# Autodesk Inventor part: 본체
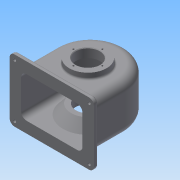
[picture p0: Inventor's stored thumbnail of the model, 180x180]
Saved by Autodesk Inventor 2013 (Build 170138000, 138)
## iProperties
Created: 2016-01
Part Number: 본체
Material: 일반
Document SubType Name: Modeling
Designer: mrc
Density: 1 g/cm^3
Author: mrc
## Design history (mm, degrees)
sketch "스케치3"
  geometry: L1 (-57, 0)-(-57, -64); L2 (57, 0)-(57, -64); L3 (-57, -64)-(57, -64); A1 r 57 centre (0, 0) between (57, 0) and (-57, 0); 1 further point
  constraints: 6 end point, 2 point on circle, 2 tangent, 1 centre point, 1 coincident, 1 parallel, 1 vertical
  dimensions: "d18" = 114 diameter of A1; "d19" = 64 distance of L1.start L1.end; "d20" = 64 distance of L2.start L2.end
extrude "돌출1" new body sketch "스케치3" distance "d21" = 77; taper "d22" = 0 deg
node "작업 평면1"
sketch "스케치5"
  geometry: L1 (-51, 0)-(-51, -64); L2 (51, 0)-(51, -64); L3 (57, -64)-(-57, -64) reference; L4 (-51, -64)-(51, -64); A1 r 51 centre (0, 0) between (51, 0) and (-51, 0); 1 further point
  constraints: 6 end point, 2 point on circle, 2 point on line, 2 tangent, 1 centre point, 1 coincident, 1 collinear, 1 parallel, 1 vertical
  dimensions: "d26" = 102 diameter of A1
extrude "돌출2" cut sketch "스케치5" distance "d27" = 67; taper "d28" = 0 deg
sketch "스케치6"
  geometry: C1 r 20 at (0, -4); A1 r 57 centre (0, 0) between (57, 0) and (-57, 0) reference
  constraints: 1 centre point, 1 vertical alignment
  dimensions: "d29" = 40 diameter of C1; "d30" = 4 distance of A1.centre C1.centre
extrude "돌출3" cut sketch "스케치6" distance "d31" = 126.75; taper "d32" = 0 deg
sketch "스케치7"
  geometry: C1 r 20 at (0, -4) reference; C2 r 31 at (0, -4); C3 r 20 at (0, -4)
  constraints: 2 centre point, 2 coincident
  dimensions: "d33" = 62 diameter of C2; "d34" = 40 diameter of C3
extrude "돌출4" join sketch "스케치7" distance "d35" = 10; taper "d36" = 0 deg
sketch "스케치8"
  geometry: C1 r 20 at (0, -4) reference; C2 r 28 at (0, -4); C3 r 20 at (0, -4)
  constraints: 2 centre point, 2 coincident
  dimensions: "d37" = 56 diameter of C2; "d38" = 40 diameter of C3
extrude "돌출5" join sketch "스케치8" distance "d39" = 16; taper "d40" = 0 deg
feature "면 기울기1" dims angle "d42" = 40 deg
sketch "스케치10"
  geometry: L1 (37.426, 5)-(24, 21) reference; L2 (-4, -2.299)-(-4, 40.983); L3 (30.899, 5)-(35.094, 0); L4 (30.899, 5)-(16, 5); L5 (24, 21)-(-32, 21) reference; L6 (0, 0)-(57, 0) reference; L7 (16, 5)-(16, 0); L8 (35.094, 0)-(16, 0)
  constraints: 10 end point, 2 perpendicular, 2 point on line, 1 collinear, 1 parallel
  dimensions: "d44" = 5 distance between parallel lines of L1 L3; "d45" = 16 distance between parallel lines of L4 L5; "d46" = 40 diameter of L7 L2
revolve "회전2" sketch "스케치10" stored, may be unused: angle "d47" = 90 deg
sketch "스케치11"
  geometry: L1 (108, 72)-(108, 5) reference; L2 (114, 0)-(0, 0) reference; L3 (114, 0)-(114, 77) reference; L4 (0, 77)-(114, 77) reference; L5 (-13, -13.5)-(127, -13.5); L6 (127, -13.5)-(127, 90.5); L7 (127, 90.5)-(-13, 90.5); L8 (-13, 90.5)-(-13, -13.5); L9 (0, 0)-(114, 0); L10 (114, 0)-(114, 77); L11 (114, 77)-(0, 77); L12 (0, 77)-(0, 0); 5 further points
  constraints: 16 end point, 4 midpoint, 4 parallel, 2 horizontal, 2 perpendicular, 1 horizontal alignment, 1 vertical alignment
  dimensions: "d48" = 140 distance of L6.end L7.end; "d50" = 104 distance of L5.end L6.end
extrude "돌출6" join sketch "스케치11" distance "d51" = 7; taper "d52" = 0 deg
node "작업 평면2"
sketch "스케치12"
  geometry: L1 (57, 77)-(-57, 77) reference; L2 (-57, 0)-(57, 0) reference; L3 (57, 0)-(57, 77) reference; C1 r 6 at (0, 38.5); 2 further points
  constraints: 1 centre point, 1 midpoint, 1 vertical alignment
  dimensions: "d54" = 12 diameter of C1; "d55" = 38.5 distance from line of L1 C1.centre
extrude "돌출7" join sketch "스케치12" stored distance "d56" = 7; taper "d57" = 0 deg
extrude "돌출8" join sketch "스케치12" distance "d58" = 6; taper "d59" = 0 deg
sketch "스케치13"
  geometry: C1 r 34.899 at (0, 0) reference; 2 further points
  constraints: 1 vertical alignment
  dimensions: "d60" = 28 distance of C1.centre point (0, 28)
hole "구멍1" sketch "스케치13" at (0, 28) diameter "d61" = 2.459; stored, may be unused: countersink angle "d65" = 90 deg, drill point angle "d67" = 118 deg; dims "d62" = 7, "d63" = 4, "d64" = 2, "d66" = 9
sketch "스케치14"
  geometry: C1 r 20 at (0, 0) reference; 2 further points
  constraints: 1 vertical alignment
  dimensions: "d71" = 24 distance of C1.centre point (0, 24)
hole "구멍2" sketch "스케치14" at (0, 24) diameter "d72" = 2.459; stored, may be unused: countersink angle "d76" = 90 deg, drill point angle "d78" = 118 deg; dims "d73" = 6, "d74" = 4, "d75" = 2, "d77" = 8
hole "구멍3" diameter "d84" = 4.459; stored, may be unused: countersink angle "d88" = 90 deg, drill point angle "d90" = 118 deg; dims "d82" = 10, "d83" = 10, "d85" = 30, "d86" = 4, "d87" = 2, "d89" = 53.25
sketch "스케치15"
  geometry: L1 (0, -57)-(0, 0) reference; L2 (90.5, -64)-(-13.5, -64) reference; 1 further point
  constraints: 1 other
  dimensions: "d91" = 38.5 distance from line of L1 point (38.5, -34); "d92" = 30 distance from line of point (38.5, -34) L2
fillet "모깎기1" dims "d93" = 8
hole "구멍4" diameter "d96" = 5; stored, may be unused: countersink angle "d100" = 90 deg, drill point angle "d102" = 0 deg; dims "d94" = 10, "d95" = 10, "d97" = 30, "d98" = 4, "d99" = 2, "d101" = 53.25
hole "구멍5" diameter "d105" = 5; stored, may be unused: countersink angle "d109" = 90 deg, drill point angle "d111" = 0 deg; dims "d103" = 10, "d104" = 10, "d106" = 30, "d107" = 4, "d108" = 2, "d110" = 53.25
hole "구멍6" diameter "d114" = 5; stored, may be unused: countersink angle "d118" = 90 deg, drill point angle "d120" = 0 deg; dims "d112" = 10, "d113" = 10, "d115" = 30, "d116" = 4, "d117" = 2, "d119" = 53.25
hole "구멍7" diameter "d123" = 5; stored, may be unused: countersink angle "d127" = 90 deg, drill point angle "d129" = 0 deg; dims "d121" = 10, "d122" = 10, "d124" = 30, "d125" = 4, "d126" = 2, "d128" = 53.25
fillet "모깎기2" dims "d130" = 3
feature "엠보싱1" dims "d18" = 114, "d19" = 64, "d20" = 64, "d131" = 0.5, "d132" = 0
fillet "모깎기3" dims "d133" = 9
fillet "모깎기5" dims "d135" = 14
fillet "모깎기6" dims "d136" = 1
fillet "모깎기7" dims "d137" = 3
chamfer "모따기1" distance "d138" = 1; stored, may be unused: second distance "d139" = 2, angle "d140" = 45 deg
chamfer "모따기2" distance "d141" = 1; stored, may be unused: second distance "d142" = 2, angle "d143" = 45 deg
fillet "모깎기8" dims "d144" = 3
fillet "모깎기9" dims "d145" = 3
fillet "모깎기10" dims "d146" = 3
node "솔리드2"
pattern_circular "원형 패턴1" dims angle "d69" = 360 deg
pattern_circular "원형 패턴2" dims angle "d80" = 360 deg
other parameters: "d25" = -5, "d53" = 57
